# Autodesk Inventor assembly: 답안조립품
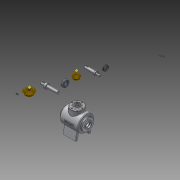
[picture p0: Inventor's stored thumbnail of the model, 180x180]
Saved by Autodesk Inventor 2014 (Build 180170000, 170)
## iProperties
Created: 2015-01
Part Number: 답안조립품
Document SubType Name: Assembly
Designer: basic
Author: basic
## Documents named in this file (15)
- C:\Users\basic\Desktop\450105V1008\450105V1008\답안조립품.iam
- C:\Users\basic\Desktop\450105V1008\450105V1008\본체.ipt
- C:\Users\basic\Desktop\450105V1008\450105V1008\M4.ipt
- C:\Users\basic\Desktop\450105V1008\450105V1008\메인 베벨기어.ipt
- C:\Users\basic\Desktop\450105V1008\450105V1008\메인 축.ipt
- 메인 축.ipt
- C:\Users\basic\Desktop\450105V1008\450105V1008\베어링 6203.ipt
- C:\Users\basic\Desktop\450105V1008\450105V1008\서브 베벨기어.ipt
- C:\Users\basic\Desktop\450105V1008\450105V1008\서브 축.ipt
- 서브 축.ipt
- C:\Users\basic\Desktop\450105V1008\450105V1008\오일실.ipt
- C:\Users\basic\Desktop\450105V1008\450105V1008\커버.ipt
- C:\Users\basic\Desktop\450105V1008\450105V1008\커버2.ipt
- C:\Users\basic\Desktop\450105V1008\450105V1008\키 4x4.ipt
- C:\Users\basic\Desktop\450105V1008\450105V1008\키 5x5.ipt
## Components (1 placed, 1 different names)
1. M4:1
